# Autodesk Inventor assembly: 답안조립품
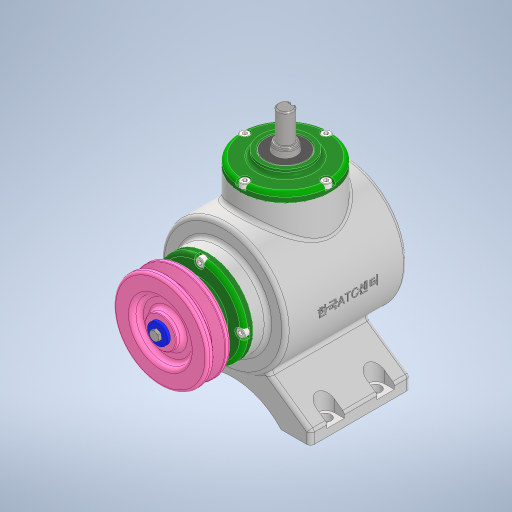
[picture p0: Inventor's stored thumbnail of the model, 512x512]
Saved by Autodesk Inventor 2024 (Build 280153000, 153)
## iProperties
Created: 2023-08
Part Number: 답안조립품
Document SubType Name: Assembly
Designer: Owner
Author: Owner
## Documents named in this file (17)
- C:\Users\Owner\Desktop\730813V1010\답안조립품.iam
- C:\Users\Owner\Desktop\730813V1010\본체.ipt
- C:\Users\Owner\Desktop\730813V1010\V-벨트풀리.ipt
- C:\Users\Owner\Desktop\730813V1010\메인 베벨기어.ipt
- C:\Users\Owner\Desktop\730813V1010\메인 축.ipt
- 메인 축.ipt
- C:\Users\Owner\Desktop\730813V1010\베어링 6203.ipt
- C:\Users\Owner\Desktop\730813V1010\볼트 M4 x 10.ipt
- C:\Users\Owner\Desktop\730813V1010\서브 베벨기어.ipt
- C:\Users\Owner\Desktop\730813V1010\서브 축.ipt
- 서브 축.ipt
- C:\Users\Owner\Desktop\730813V1010\오일실 17 x 32 x 8.ipt
- C:\Users\Owner\Desktop\730813V1010\와셔 4 x 16.ipt
- C:\Users\Owner\Desktop\730813V1010\육각볼트 M4 x 8.ipt
- C:\Users\Owner\Desktop\730813V1010\커버.ipt
- C:\Users\Owner\Desktop\730813V1010\키 4 x 4 x 14.ipt
- C:\Users\Owner\Desktop\730813V1010\키 5 x 5 x 14.ipt
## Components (1 placed, 1 different names)
1. V-벨트풀리:1
